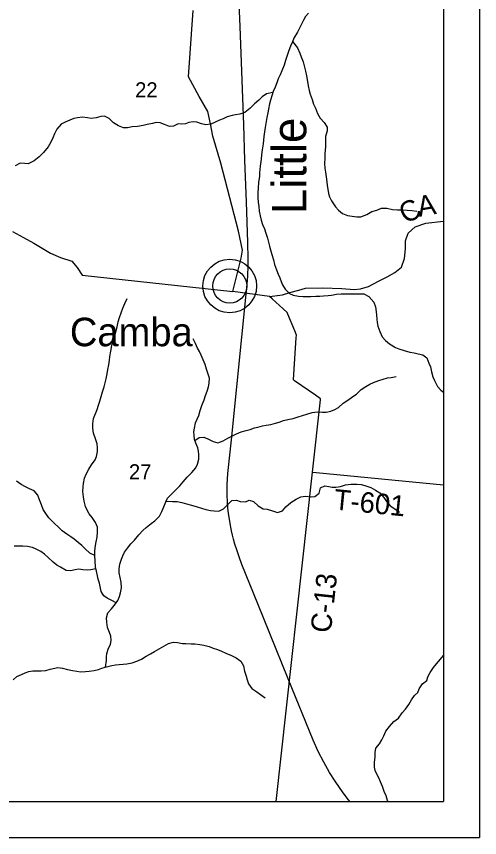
# Model space of a CAD drawing. Extents: x 0 to 34, y 0 to 22.
# Drawn here: x 7.716 to 9, y 14 to 16.276 of the extents above; entities that cross this region are included whole.
import ezdxf

# ---------------------------------------------------------------- set-up
doc = ezdxf.new("R2010")
doc.units = 0
for name, color, linetype in [('GM_X_County_Road', 7, 'Continuous'), ('GM_X_County_Road_Text', 7, 'Continuous'), ('GM_X_Major_River', 7, 'Continuous'), ('GM_X_Major_River_Text', 7, 'Continuous'), ('GM_X_Minor_River', 7, 'Continuous'), ('GM_X_Rail_Line', 7, 'Continuous'), ('GM_X_Section_Text', 7, 'Continuous'), ('GM_X_Township_Road', 7, 'Continuous'), ('GM_X_Township_Road_Text', 7, 'Continuous'), ('GM_X_Unincorporated', 7, 'Continuous'), ('GM_X_Unincorporated_Location', 7, 'Continuous'), ('GM_X_Unincorporated_Text', 7, 'Continuous'), ('SH_Data', 7, 'Continuous')]:
    doc.layers.add(name, color=color, linetype=linetype)

msp = doc.modelspace()

# ---------------------------------------------------------------- linework, layer by layer
at = {"layer": 'GM_X_County_Road'}
msp.add_line((8.4179, 15.4996), (8.3159, 15.5133), dxfattribs=at)
for points in [[(8.3159, 15.5133), (8.3315, 15.5763), (8.339, 15.6059), (8.343, 15.6283), (8.3315, 15.6809), (8.2826, 15.8695), (8.2611, 15.9441), (8.2538, 15.9778), (8.2465, 16.0123), (8.2224, 16.0543), (8.1931, 16.1084), (8.2061, 16.2922)], [(8.4179, 15.4996), (8.454, 15.5044), (8.4741, 15.511), (8.499, 15.5172), (8.5179, 15.5229), (8.5659, 15.5236), (8.6178, 15.5215), (8.6526, 15.5194), (8.67, 15.521), (8.6923, 15.5272), (8.7213, 15.5429), (8.7436, 15.554), (8.7655, 15.5666), (8.784, 15.5807), (8.7922, 15.6046), (8.7944, 15.6316), (8.7946, 15.6539), (8.8021, 15.6748), (8.8217, 15.6928), (8.8508, 15.7031), (8.9, 15.7081)], [(7.7057, 15.6795), (7.7361, 15.6629), (7.7649, 15.6475), (7.8108, 15.6197), (7.8385, 15.608), (7.8703, 15.598), (7.8847, 15.5798), (7.8981, 15.559), (8.3159, 15.5133)], [(8.4364, 14.1), (8.5371, 15.0129), (8.5592, 15.2132), (8.5595, 15.2158), (8.5451, 15.2259), (8.4873, 15.2663), (8.484, 15.2686), (8.4851, 15.2847), (8.4918, 15.3852), (8.4923, 15.3927), (8.4876, 15.4044), (8.4686, 15.451), (8.4669, 15.455), (8.4552, 15.4657), (8.4254, 15.4928), (8.4179, 15.4996)]]:
    msp.add_lwpolyline(points, dxfattribs=at)
at = {"layer": 'GM_X_Major_River'}
for points in [[(8.5255, 16.2852), (8.5174, 16.2754), (8.5124, 16.2652), (8.5021, 16.2452), (8.4951, 16.2324), (8.4855, 16.2154), (8.4813, 16.2056), (8.4759, 16.1939), (8.4713, 16.1818), (8.4666, 16.1678), (8.4623, 16.1534), (8.4584, 16.1409), (8.4522, 16.1254), (8.4476, 16.1141), (8.4422, 16.1032), (8.4384, 16.0922), (8.433, 16.0801), (8.4283, 16.068), (8.4248, 16.0582), (8.4202, 16.0438), (8.4178, 16.0336), (8.4147, 16.0189), (8.413, 16.0083), (8.4107, 15.9958), (8.4079, 15.9795), (8.4059, 15.9681), (8.4043, 15.9564), (8.4023, 15.9431), (8.401, 15.9333), (8.3998, 15.9227), (8.3978, 15.906), (8.3958, 15.892), (8.3942, 15.8799), (8.3921, 15.861), (8.3904, 15.8428), (8.3896, 15.8329), (8.3875, 15.8155), (8.3863, 15.8011), (8.3858, 15.7871), (8.3857, 15.7731), (8.3867, 15.7609), (8.3881, 15.7488), (8.3895, 15.7359), (8.3916, 15.7234), (8.3946, 15.7116), (8.3986, 15.6994), (8.4042, 15.6868), (8.4078, 15.6751), (8.4119, 15.6614), (8.4148, 15.6507), (8.4177, 15.639), (8.4203, 15.6294), (8.424, 15.6158), (8.4284, 15.6009), (8.4316, 15.5884), (8.4372, 15.5739), (8.442, 15.5618), (8.4461, 15.5511), (8.4501, 15.5416), (8.4538, 15.5321), (8.4613, 15.5199), (8.4736, 15.5077), (8.4834, 15.5034), (8.4978, 15.5002), (8.511, 15.5001), (8.5208, 15.4996)], [(8.5208, 15.4996), (8.5322, 15.4995), (8.5461, 15.5002), (8.5575, 15.5008), (8.5673, 15.5011), (8.5802, 15.5025), (8.59, 15.5036), (8.6033, 15.5065), (8.6165, 15.5075), (8.6418, 15.5073), (8.6562, 15.5068), (8.6675, 15.5074), (8.6796, 15.5066), (8.6928, 15.5), (8.707, 15.4843), (8.7114, 15.4706), (8.7132, 15.4574), (8.7142, 15.4475), (8.7149, 15.4372), (8.7159, 15.4274), (8.7177, 15.4175), (8.7233, 15.403), (8.7303, 15.3882), (8.7397, 15.3775), (8.7506, 15.3687), (8.7667, 15.3587), (8.7765, 15.3548), (8.7912, 15.3497), (8.8067, 15.3458), (8.8188, 15.3431), (8.8297, 15.3411), (8.8429, 15.3379), (8.8538, 15.3295), (8.8597, 15.315), (8.8638, 15.3044), (8.867, 15.2907), (8.8707, 15.277), (8.8748, 15.2671), (8.8833, 15.2504), (8.8927, 15.24), (8.9, 15.2346)]]:
    msp.add_lwpolyline(points, dxfattribs=at)
at = {"layer": 'GM_X_Minor_River'}
for points in [[(8.4816, 16.2064), (8.495, 16.1885), (8.5014, 16.174), (8.5059, 16.1642), (8.5107, 16.1505), (8.5174, 16.1239), (8.5204, 16.1114), (8.5222, 16.1008), (8.5252, 16.0833), (8.5278, 16.0708), (8.5304, 16.0606), (8.5356, 16.0454), (8.5401, 16.0328), (8.5453, 16.0218), (8.5505, 16.0066), (8.558, 15.9941), (8.5697, 15.9819), (8.578, 15.969), (8.5775, 15.9588), (8.5733, 15.9429), (8.5729, 15.9247), (8.5728, 15.9152), (8.5712, 15.8955), (8.5712, 15.8834), (8.5703, 15.8682), (8.5714, 15.8553), (8.5729, 15.8443), (8.5747, 15.8318), (8.5766, 15.8177), (8.5776, 15.8071), (8.5795, 15.7973), (8.5817, 15.7855), (8.5843, 15.776), (8.5896, 15.7646), (8.6004, 15.7486), (8.6087, 15.7391), (8.62, 15.7296), (8.6336, 15.7239), (8.6472, 15.7223), (8.66, 15.7207), (8.6706, 15.7203), (8.6873, 15.7274), (8.7017, 15.7353), (8.7153, 15.7394), (8.7282, 15.7447), (8.7425, 15.7442), (8.7588, 15.7411), (8.7727, 15.7399), (8.7879, 15.7402), (8.7996, 15.739), (8.8124, 15.7378), (8.8264, 15.7366)], [(8.4272, 16.0649), (8.409, 16.0611), (8.3973, 16.0532), (8.3878, 16.0442), (8.376, 16.034), (8.3635, 16.0211), (8.3495, 16.0098), (8.3359, 16.0046), (8.3238, 16.0035), (8.3139, 16.0017), (8.3007, 15.9972), (8.2893, 15.9923), (8.2795, 15.9885), (8.2651, 15.9818), (8.2552, 15.9773), (8.2412, 15.9758), (8.2295, 15.9785), (8.2159, 15.9824), (8.2061, 15.9839), (8.1944, 15.9821), (8.1846, 15.9787), (8.1747, 15.9773), (8.1645, 15.9784), (8.1516, 15.9721), (8.1403, 15.971), (8.1263, 15.9767), (8.115, 15.9813), (8.1041, 15.9818), (8.0935, 15.9788), (8.0787, 15.9762), (8.0677, 15.9732), (8.0519, 15.971), (8.0371, 15.9696), (8.0243, 15.9673), (8.0129, 15.967), (7.9993, 15.9724), (7.9854, 15.9812), (7.973, 15.993), (7.9609, 15.9991), (7.9503, 15.9984), (7.9371, 15.995), (7.9235, 15.9928), (7.9133, 15.9951), (7.8997, 15.9963), (7.886, 15.9945), (7.8758, 15.9926), (7.8645, 15.9885), (7.8516, 15.9829), (7.8399, 15.9776), (7.8281, 15.9637), (7.822, 15.9501), (7.817, 15.9398), (7.8113, 15.9277), (7.8044, 15.9141), (7.7915, 15.8986), (7.7794, 15.8869), (7.7653, 15.8756), (7.7491, 15.8674), (7.7392, 15.8686), (7.7268, 15.869), (7.7127, 15.8615)], [(7.9929, 14.6503), (7.9812, 14.6567), (7.968, 14.6632), (7.9582, 14.6701), (7.9514, 14.6823), (7.9484, 14.6955), (7.9462, 14.705), (7.9429, 14.716), (7.941, 14.7255), (7.9381, 14.7384), (7.9358, 14.7502), (7.9344, 14.7661), (7.9333, 14.7817), (7.9337, 14.7923), (7.9346, 14.804), (7.9369, 14.8199), (7.94, 14.8328), (7.9415, 14.8468), (7.9408, 14.8605), (7.9356, 14.8734), (7.9262, 14.8871), (7.918, 14.8977), (7.9123, 14.9072), (7.9082, 14.9178), (7.9041, 14.9323), (7.9019, 14.9444), (7.9008, 14.9588), (7.9013, 14.9717), (7.9021, 14.9815), (7.9048, 14.9959), (7.9097, 15.0077), (7.917, 15.0209), (7.9246, 15.0334), (7.9345, 15.0466), (7.9383, 15.0564), (7.941, 15.0705), (7.9414, 15.0799), (7.9403, 15.0917), (7.9359, 15.1053), (7.9303, 15.1209), (7.9281, 15.1346), (7.9285, 15.1467), (7.9304, 15.1615), (7.9404, 15.1861), (7.9442, 15.1986), (7.9477, 15.2099), (7.9511, 15.2224), (7.9553, 15.2357), (7.9592, 15.2489), (7.9626, 15.2606), (7.9653, 15.2716), (7.968, 15.2853), (7.97, 15.2974), (7.9727, 15.3099), (7.9742, 15.3228), (7.9754, 15.3322), (7.9773, 15.3432), (7.9785, 15.3531), (7.9808, 15.3648), (7.985, 15.3784), (7.9885, 15.3883), (7.9923, 15.4019), (7.9954, 15.4159), (7.9985, 15.4295), (8.002, 15.4413), (8.0069, 15.4541), (8.0115, 15.4674), (8.0165, 15.4806), (8.0237, 15.4943)], [(7.9632, 14.4721), (7.9661, 14.4908), (7.9657, 14.5006), (7.9665, 14.5105), (7.9711, 14.5249), (7.9772, 14.5347), (7.9792, 14.5476), (7.9781, 14.5582), (7.9747, 14.5681), (7.9687, 14.5825), (7.9665, 14.5969), (7.9658, 14.609), (7.9697, 14.6227), (7.9803, 14.634), (7.9909, 14.6476), (7.9978, 14.6574), (8.002, 14.668), (8.0051, 14.6782), (8.0078, 14.6919), (8.0067, 14.7082), (8.0037, 14.7211), (8.0011, 14.734), (8.0012, 14.745), (8.0028, 14.7578), (8.0077, 14.7715), (8.0116, 14.7813), (8.0161, 14.7915), (8.0241, 14.8021), (8.0332, 14.8138), (8.0439, 14.8244), (8.0553, 14.8387), (8.0667, 14.8508), (8.0761, 14.8591), (8.0902, 14.8704), (8.1, 14.8783), (8.1129, 14.8911), (8.1198, 14.904), (8.1248, 14.9165), (8.1305, 14.9305), (8.1355, 14.9407), (8.1476, 14.9535), (8.1594, 14.9648), (8.1692, 14.975), (8.1787, 14.9856), (8.1898, 14.9988), (8.2023, 15.012), (8.2133, 15.0249), (8.2186, 15.0347), (8.2221, 15.0491), (8.2222, 15.0616), (8.2211, 15.0711), (8.2188, 15.0806), (8.2136, 15.0935), (8.2099, 15.1037), (8.2088, 15.1151), (8.2084, 15.1246), (8.2096, 15.1344), (8.2131, 15.1492), (8.2173, 15.1594), (8.2219, 15.17), (8.2257, 15.1833), (8.2303, 15.1976), (8.2364, 15.2135), (8.2406, 15.2256), (8.2452, 15.237), (8.2483, 15.2491), (8.2506, 15.259), (8.2518, 15.273), (8.2473, 15.2874), (8.2436, 15.298), (8.2395, 15.3109), (8.2343, 15.3239), (8.2279, 15.3375), (8.2234, 15.347), (8.2181, 15.3569), (8.2122, 15.3691), (8.2065, 15.3824)], [(8.211, 15.1007), (8.2231, 15.1086), (8.2356, 15.1101), (8.2473, 15.1055), (8.2616, 15.0978), (8.2748, 15.094), (8.2896, 15.0992), (8.3025, 15.1071), (8.3154, 15.1131), (8.3263, 15.1187), (8.3396, 15.1244), (8.3528, 15.1281), (8.3638, 15.1315), (8.3759, 15.1352), (8.3858, 15.1378), (8.3979, 15.1408), (8.4085, 15.1434), (8.4213, 15.1448), (8.4342, 15.1482), (8.4448, 15.1516), (8.4569, 15.1557), (8.469, 15.1587), (8.4834, 15.1616), (8.4974, 15.1661), (8.5095, 15.1702), (8.5216, 15.1736), (8.5356, 15.1777), (8.5511, 15.1803), (8.5647, 15.1791), (8.5745, 15.179), (8.5878, 15.1816), (8.5988, 15.1861), (8.6086, 15.1921), (8.6219, 15.2038), (8.6348, 15.2121), (8.6488, 15.2223), (8.659, 15.2291), (8.6719, 15.2415), (8.6848, 15.2506), (8.6958, 15.2569), (8.7057, 15.2611), (8.7204, 15.2667), (8.7325, 15.2708), (8.7446, 15.2745), (8.7549, 15.2756), (8.7692, 15.2775)], [(7.9333, 14.7817), (7.9194, 14.7885), (7.907, 14.8003), (7.8972, 14.8091), (7.8874, 14.8182), (7.8765, 14.827), (7.8667, 14.8331), (7.8561, 14.8408), (7.8433, 14.8503), (7.8335, 14.8594), (7.8203, 14.8728), (7.8064, 14.8861), (7.7978, 14.8983), (7.7906, 14.9097), (7.7854, 14.9222), (7.7802, 14.9359), (7.7761, 14.9491), (7.7652, 14.9606), (7.7527, 14.9667), (7.7418, 14.9724), (7.7293, 14.9785), (7.7161, 14.9881)], [(8.1315, 14.9326), (8.1487, 14.9315), (8.1623, 14.9311), (8.1751, 14.9284), (8.1879, 14.9249), (8.2015, 14.9214), (8.217, 14.9168), (8.2295, 14.9126), (8.2412, 14.9095), (8.2544, 14.9068), (8.2646, 14.9052), (8.2774, 14.9044), (8.2903, 14.9112), (8.3138, 14.9346), (8.3263, 14.9353), (8.3369, 14.9318), (8.3512, 14.9302), (8.3618, 14.9355), (8.3735, 14.9313), (8.3867, 14.9195), (8.4003, 14.9114), (8.4116, 14.9106), (8.426, 14.9056), (8.4399, 14.9007), (8.4535, 14.9059), (8.4634, 14.9168), (8.4767, 14.9285), (8.4915, 14.9379), (8.5047, 14.9447), (8.5172, 14.9462), (8.5331, 14.9446), (8.5433, 14.9457), (8.555, 14.9543), (8.5593, 14.9691), (8.5714, 14.9751), (8.582, 14.9735), (8.5918, 14.9712), (8.602, 14.9712), (8.6145, 14.9734), (8.6288, 14.9775), (8.6436, 14.9797), (8.6595, 14.9796), (8.6719, 14.9785), (8.6817, 14.9761), (8.6984, 14.97), (8.7116, 14.9631), (8.724, 14.9551), (8.7345, 14.9429), (8.7424, 14.9311), (8.7526, 14.9193), (8.7654, 14.9113), (8.7782, 14.9022)], [(7.9368, 14.7451), (7.9222, 14.7419), (7.9124, 14.7412), (7.9006, 14.742), (7.8897, 14.7436), (7.8795, 14.7417), (7.8666, 14.7391), (7.8542, 14.7407), (7.8383, 14.7491), (7.8281, 14.7552), (7.818, 14.7632), (7.8044, 14.7766), (7.7939, 14.7857), (7.7837, 14.7929), (7.7709, 14.7998), (7.7607, 14.8037), (7.7467, 14.8068), (7.7343, 14.8076), (7.7207, 14.808), (7.7097, 14.8081)], [(7.7073, 14.4374), (7.7179, 14.4461), (7.7308, 14.4521), (7.7407, 14.4562), (7.7509, 14.4603), (7.7615, 14.4625), (7.7747, 14.4621), (7.7845, 14.4621), (7.7978, 14.4631), (7.8099, 14.4669), (7.8311, 14.4713), (7.8443, 14.4697), (7.8579, 14.4663), (7.8715, 14.4632), (7.8839, 14.4608), (7.8938, 14.4597), (7.9074, 14.46), (7.918, 14.4615), (7.9316, 14.4633), (7.9437, 14.4659), (7.9535, 14.4692), (7.9664, 14.473), (7.9808, 14.4767), (7.9906, 14.4786), (8.0012, 14.4793), (8.0121, 14.4804), (8.0224, 14.4814), (8.0375, 14.4844), (8.05, 14.4885), (8.0632, 14.4945), (8.0757, 14.5024), (8.0882, 14.5096), (8.0992, 14.516), (8.1121, 14.5227), (8.1246, 14.5306), (8.1379, 14.5378), (8.1515, 14.5419), (8.1632, 14.5407), (8.1764, 14.538), (8.1862, 14.5379), (8.2006, 14.5371), (8.2112, 14.5367), (8.2244, 14.5351), (8.2361, 14.5332), (8.2508, 14.5293), (8.2614, 14.5251), (8.2735, 14.5212), (8.2844, 14.5166), (8.2969, 14.5113), (8.3127, 14.5044), (8.3255, 14.4983), (8.338, 14.4887), (8.3455, 14.4762), (8.3488, 14.4614), (8.3529, 14.447), (8.3555, 14.4375), (8.3592, 14.4257), (8.369, 14.4128), (8.383, 14.404), (8.3927, 14.3968), (8.4056, 14.3876)], [(8.7463, 14.1), (8.7448, 14.103), (8.7407, 14.1155), (8.7359, 14.1277), (8.7307, 14.1417), (8.7254, 14.1542), (8.7206, 14.1653), (8.7153, 14.1759), (8.7108, 14.1858), (8.709, 14.1956), (8.709, 14.2089), (8.7106, 14.2233), (8.711, 14.2354), (8.7122, 14.2479), (8.7225, 14.2596), (8.7293, 14.2706), (8.7343, 14.2819), (8.74, 14.2948), (8.7499, 14.3076), (8.7628, 14.3216), (8.7753, 14.3314), (8.7856, 14.3454), (8.7943, 14.3556), (8.8035, 14.3688), (8.8111, 14.3816), (8.8194, 14.3937), (8.8293, 14.4024), (8.8327, 14.4126), (8.8422, 14.4258), (8.8536, 14.4353), (8.8567, 14.4451), (8.8632, 14.4576), (8.8719, 14.4712), (8.881, 14.4818), (8.8917, 14.4946), (8.9, 14.505)]]:
    msp.add_lwpolyline(points, dxfattribs=at)
at = {"layer": 'GM_X_Rail_Line'}
msp.add_lwpolyline([(8.6407, 14.1), (8.637, 14.1044), (8.6223, 14.1238), (8.5993, 14.1561), (8.584, 14.1806), (8.5679, 14.2092), (8.5529, 14.2382), (8.5389, 14.2697), (8.4696, 14.4402), (8.4189, 14.5655), (8.3856, 14.648), (8.3415, 14.7565), (8.3336, 14.7778), (8.327, 14.7972), (8.3221, 14.8128), (8.3181, 14.8275), (8.3153, 14.8383), (8.3127, 14.8501), (8.3078, 14.8756), (8.3044, 14.8991), (8.3027, 14.9134), (8.3013, 14.9323), (8.3006, 14.9473), (8.3006, 14.9638), (8.3008, 14.9796), (8.3013, 14.9932), (8.3023, 15.0091), (8.312, 15.1025), (8.3563, 15.5337), (8.3578, 15.5566), (8.3585, 15.5847), (8.3588, 15.6053), (8.358, 15.6498), (8.3541, 15.7619), (8.3496, 15.8777), (8.3462, 15.9757), (8.336, 16.2482), (8.3302, 16.398)], dxfattribs=at)
at = {"layer": 'GM_X_Township_Road'}
msp.add_lwpolyline([(8.5371, 15.0129), (8.547, 15.0118), (8.9, 14.9777)], dxfattribs=at)
at = {"layer": 'GM_X_Unincorporated'}
for radius in [0.0744, 0.0472]:
    msp.add_circle((8.3075, 15.5288), radius, dxfattribs=at)
at = {"layer": 'GM_X_Unincorporated_Location'}
msp.add_line((8.3075, 15.5288), (8.3075, 15.5288), dxfattribs=at)
at = {"layer": 'SH_Data'}
for p, q in [((9, 21), (9, 14)), ((8.9, 20.9), (8.9, 14.1)), ((2.1, 14.1), (8.9, 14.1)), ((2, 14), (9, 14))]:
    msp.add_line(p, q, dxfattribs=at)

# ---------------------------------------------------------------- texts
at = {"layer": 'GM_X_County_Road_Text'}
for s, height, rotation, p in [('A', 0.0568, 9.9546, (8.8324, 15.7202)), ('C', 0.0568, 28.7108, (8.7961, 15.6994)), ('C-13', 0.05682, 83.8109, (8.5876, 14.5655))]:
    msp.add_text(s, height=height, rotation=rotation, dxfattribs=at).set_placement(p)
at = {"layer": 'GM_X_Major_River_Text'}
msp.add_text('Little', height=0.09471, rotation=89.9999, dxfattribs=at).set_placement((8.5198, 15.7278))
at = {"layer": 'GM_X_Section_Text'}
for s, p in [('22', (8.0453, 16.0515)), ('27', (8.0282, 14.9928))]:
    msp.add_text(s, height=0.04186, rotation=0, dxfattribs=at).set_placement(p)
at = {"layer": 'GM_X_Township_Road_Text'}
msp.add_text('T-601', height=0.05682, rotation=354.3731, dxfattribs=at).set_placement((8.594, 14.9096))
at = {"layer": 'GM_X_Unincorporated_Text'}
msp.add_text('Camba', height=0.07898, rotation=0, dxfattribs=at).set_placement((7.8645, 15.3619))

doc.saveas('drawing.dxf')
